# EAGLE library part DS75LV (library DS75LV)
low-voltage (1.7V to 3.7V) digital thermometer and thermostat
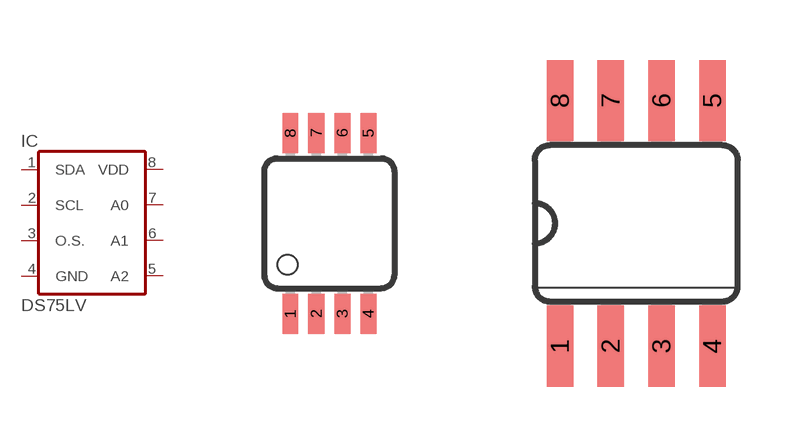
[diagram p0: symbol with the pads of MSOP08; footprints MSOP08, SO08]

Designator prefix IC

## DS75LVU  [MSOP08]
1  SDA  pas
2  SCL  pas
3  O.S.  pas
4  GND  nc
5  A2  pwr
6  A1  pwr
7  A0  out
8  VDD  out

## DS75LVS  [SO08]
Pads as for MSOP08

## Footprint MSOP08 (pad centres in mm)
micro Small Outline Package 8
smd 0.4 x 1: 1 -0.976,-2.263; 2 -0.326,-2.263; 3 0.324,-2.263; 4 0.974,-2.263; 5 0.974,2.262; 6 0.324,2.262; 7 -0.326,2.262; 8 -0.976,2.262

## Footprint SO08 (pad centres in mm)
Small Outline Package 8
smd 0.66 x 2.032: 1 -1.905,-3.073; 2 -0.635,-3.073; 3 0.635,-3.073; 4 1.905,-3.073; 5 1.905,3.073; 6 0.635,3.073; 7 -0.635,3.073; 8 -1.905,3.073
